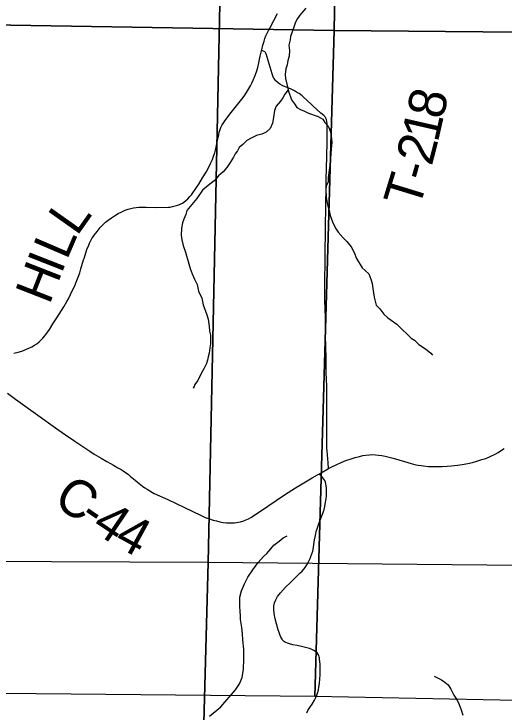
# Model space of a CAD drawing. Extents: x -19.9 to 41.9, y 0 to 32.3.
# Drawn here: x 5.525 to 6.268, y 14.677 to 15.736 of the extents above; entities that cross this region are included whole.
import ezdxf

# ---------------------------------------------------------------- set-up
doc = ezdxf.new("R2010")
doc.units = 0
for name, color, linetype in [('GM_X_Corporation', 7, 'Continuous'), ('GM_X_County_Road', 7, 'Continuous'), ('GM_X_County_Road_Text', 7, 'Continuous'), ('GM_X_Minor_River', 7, 'Continuous'), ('GM_X_Section', 7, 'Continuous'), ('GM_X_Township_Road', 7, 'Continuous'), ('GM_X_Township_Road_Text', 7, 'Continuous')]:
    doc.layers.add(name, color=color, linetype=linetype)

msp = doc.modelspace()

# ---------------------------------------------------------------- linework, layer by layer
at = {"layer": 'GM_X_Corporation'}
for points in [[(5.8404, 15.9209), (5.8188, 14.9036), (4.9872, 14.9075), (5.0009, 15.8404), (5.0026, 15.928)], [(6.8522, 15.9041), (6.8226, 14.894), (5.8188, 14.9036), (5.8404, 15.9209)], [(4.9783, 14.1), (5.7974, 14.1), (5.8188, 14.9036), (4.9872, 14.9075), (4.9863, 14.8396)], [(5.7974, 14.1), (6.8053, 14.1), (6.8226, 14.894), (5.8188, 14.9036)]]:
    msp.add_lwpolyline(points, close=True, dxfattribs=at)
at = {"layer": 'GM_X_County_Road'}
msp.add_line((5.9877, 15.0383), (6.0017, 15.0465), dxfattribs=at)
for points in [[(5.5146, 15.1607), (5.5269, 15.1516), (5.5605, 15.1273), (5.5873, 15.1082), (5.6025, 15.0977), (5.6169, 15.088), (5.6396, 15.0726), (5.6463, 15.0683), (5.657, 15.062), (5.6654, 15.0572), (5.6708, 15.0541), (5.6753, 15.0515), (5.682, 15.0476), (5.687, 15.0447), (5.6902, 15.0427), (5.6981, 15.0371), (5.7007, 15.035), (5.7083, 15.0289), (5.7145, 15.0238), (5.7193, 15.0198), (5.7229, 15.0172), (5.7266, 15.0148), (5.7346, 15.01), (5.7372, 15.0087), (5.7577, 14.9992), (5.7832, 14.9872), (5.8073, 14.9756), (5.8146, 14.9723), (5.8197, 14.9704), (5.8264, 14.9682), (5.8316, 14.9668), (5.8367, 14.9656), (5.842, 14.9646), (5.8468, 14.9641), (5.8511, 14.9639), (5.8589, 14.9641), (5.8651, 14.965), (5.8682, 14.9657), (5.873, 14.9671), (5.8753, 14.9679), (5.88, 14.97), (5.8838, 14.972), (5.8863, 14.9735), (5.9095, 14.9892), (5.9349, 15.0065), (5.9515, 15.0173), (5.9666, 15.0264), (5.9768, 15.0324), (5.9848, 15.0367), (5.9877, 15.0383)], [(6.0017, 15.0465), (6.0068, 15.049), (6.0142, 15.0527), (6.0208, 15.0556), (6.028, 15.0584), (6.0359, 15.0611), (6.0419, 15.063), (6.0484, 15.0648), (6.0537, 15.066), (6.0581, 15.0667), (6.0636, 15.0673), (6.0674, 15.0675), (6.0726, 15.0673), (6.0775, 15.0668), (6.0825, 15.0661), (6.0876, 15.0651), (6.0916, 15.0641), (6.0998, 15.0619), (6.1165, 15.0568), (6.127, 15.0538), (6.1302, 15.053), (6.1339, 15.0522), (6.1375, 15.0513), (6.142, 15.0507), (6.1458, 15.0502), (6.1531, 15.0495), (6.1586, 15.0494), (6.1673, 15.0493), (6.1737, 15.0494), (6.1815, 15.0498), (6.1882, 15.0503), (6.1971, 15.0514), (6.2043, 15.0525), (6.213, 15.0541), (6.2199, 15.0557), (6.2265, 15.0575), (6.234, 15.0598), (6.2401, 15.0618), (6.2454, 15.0639), (6.2479, 15.065), (6.2542, 15.0683), (6.259, 15.0709), (6.2625, 15.0731), (6.2678, 15.0766)]]:
    msp.add_lwpolyline(points, dxfattribs=at)
at = {"layer": 'GM_X_Minor_River'}
for points in [[(5.9671, 15.7447), (5.9582, 15.7343), (5.9534, 15.7274), (5.9508, 15.722), (5.9483, 15.7143), (5.9439, 15.7017), (5.9432, 15.6964), (5.9414, 15.6884), (5.9423, 15.6807), (5.9417, 15.672), (5.9399, 15.6651), (5.9388, 15.6586), (5.937, 15.6529), (5.936, 15.6441), (5.9361, 15.638), (5.9389, 15.6274), (5.9406, 15.6187), (5.9453, 15.6054), (5.9499, 15.5998), (5.9534, 15.5941), (5.9588, 15.5908), (5.9652, 15.5882), (5.971, 15.5852), (5.9858, 15.5805), (5.9927, 15.5764), (5.9958, 15.5715), (6.0008, 15.5659), (6.0031, 15.561), (6.0051, 15.5549), (6.0064, 15.5412), (6.0054, 15.5306), (6.0045, 15.5172), (6.0046, 15.5119), (6.0028, 15.5027), (6.0011, 15.4879), (6.0009, 15.4814), (5.9979, 15.4749), (5.9976, 15.4699), (5.9978, 15.4577), (6.0002, 15.4467), (6.0023, 15.4376), (6.0039, 15.4301), (6.0074, 15.4206), (6.0121, 15.4108), (6.0164, 15.4051), (6.0237, 15.3965), (6.0294, 15.3908), (6.036, 15.3826), (6.0403, 15.3739), (6.0442, 15.3652), (6.0524, 15.3508), (6.0573, 15.3467), (6.0627, 15.3415), (6.0655, 15.3335), (6.0678, 15.3271), (6.0687, 15.3195), (6.0696, 15.313), (6.0708, 15.3062), (6.0736, 15.2941), (6.0794, 15.2884), (6.0852, 15.2805), (6.0913, 15.2749), (6.0963, 15.2712), (6.1051, 15.2652), (6.1132, 15.2573), (6.1208, 15.2502), (6.1266, 15.2442), (6.1319, 15.2409), (6.1385, 15.2345), (6.1488, 15.2278), (6.1565, 15.2214), (6.1591, 15.2183)], [(5.9402, 15.6207), (5.9353, 15.614), (5.932, 15.6087), (5.9287, 15.6037), (5.9223, 15.5959), (5.9194, 15.5894), (5.9187, 15.5826), (5.9177, 15.5757), (5.9167, 15.57), (5.913, 15.5619), (5.907, 15.5565), (5.9006, 15.5538), (5.8923, 15.5513), (5.8844, 15.5474), (5.8777, 15.5439), (5.8717, 15.5377), (5.8661, 15.5334), (5.8635, 15.5285), (5.8602, 15.5235), (5.8572, 15.5185), (5.8524, 15.5108), (5.8472, 15.5031), (5.8416, 15.4965), (5.8349, 15.4904), (5.8282, 15.4826), (5.8192, 15.4757), (5.8106, 15.4687), (5.8017, 15.456), (5.7917, 15.444), (5.7868, 15.4379), (5.785, 15.4318), (5.7821, 15.4245), (5.7803, 15.4191), (5.7785, 15.4111), (5.7779, 15.4004), (5.7792, 15.3932), (5.7812, 15.3845), (5.7847, 15.3747), (5.7863, 15.369), (5.7875, 15.364), (5.7895, 15.3568), (5.7915, 15.35), (5.7947, 15.3417), (5.7982, 15.3337), (5.8021, 15.3254), (5.8045, 15.3152), (5.8092, 15.3046), (5.8116, 15.2947), (5.8172, 15.2796), (5.8191, 15.2728), (5.8204, 15.2621), (5.8213, 15.2549), (5.8225, 15.2488), (5.8227, 15.2355), (5.8217, 15.2294), (5.8206, 15.2214), (5.8192, 15.2157), (5.8182, 15.2107), (5.8163, 15.2057), (5.8123, 15.1977), (5.8086, 15.1904), (5.806, 15.185), (5.8027, 15.1793), (5.799, 15.1739), (5.7968, 15.1685), (5.7971, 15.1704)], [(5.873, 14.7723), (5.8717, 14.7867), (5.8712, 14.7955), (5.8699, 14.8053), (5.8682, 14.8171), (5.8681, 14.8224), (5.8676, 14.8301), (5.8671, 14.8373), (5.867, 14.8441), (5.8673, 14.8514), (5.8698, 14.8609), (5.8742, 14.8713), (5.8794, 14.8816), (5.8868, 14.8928), (5.8949, 14.9039), (5.9031, 14.9128), (5.908, 14.9174), (5.9139, 14.9244), (5.9188, 14.9302), (5.9266, 14.9364), (5.933, 14.9414), (5.9386, 14.9441)], [(5.8211, 14.6706), (5.8323, 14.6796), (5.8383, 14.685), (5.8472, 14.6954), (5.8543, 14.7035), (5.8606, 14.7108), (5.8666, 14.72), (5.8706, 14.7292), (5.8727, 14.7422), (5.8732, 14.7574), (5.873, 14.7723)], [(6.1617, 14.7316), (6.1728, 14.7257), (6.1781, 14.7224), (6.1831, 14.7183), (6.187, 14.7119), (6.1917, 14.7028), (6.1967, 14.6949), (6.1994, 14.6884), (6.2026, 14.6805), (6.2054, 14.6722)]]:
    msp.add_lwpolyline(points, dxfattribs=at)
at = {"layer": 'GM_X_Section'}
for points in [[(5.0099, 16.7619), (6.0276, 16.7357), (6.0103, 15.7106), (4.9984, 15.7274)], [(6.0276, 16.7357), (7.0463, 16.7153), (7.0239, 15.7019), (6.0103, 15.7106)], [(6.0103, 15.7106), (5.9806, 14.7005), (4.9768, 14.7102), (4.9984, 15.7274)], [(7.0239, 15.7019), (7.0016, 14.6805), (5.9806, 14.7005), (6.0103, 15.7106)]]:
    msp.add_lwpolyline(points, close=True, dxfattribs=at)
at = {"layer": 'GM_X_Township_Road'}
msp.add_line((5.9877, 15.0383), (6.0017, 15.0465), dxfattribs=at)
for points in [[(5.5242, 15.2212), (5.5307, 15.2228), (5.5363, 15.2244), (5.5401, 15.2257), (5.5472, 15.2287), (5.5515, 15.2308), (5.5559, 15.2333), (5.5593, 15.2357), (5.563, 15.2387), (5.5653, 15.2409), (5.5684, 15.2441), (5.5712, 15.2475), (5.5742, 15.2515), (5.5783, 15.2573), (5.5837, 15.2658), (5.5894, 15.2748), (5.6002, 15.2917), (5.6049, 15.2995), (5.6074, 15.304), (5.6105, 15.3103), (5.6173, 15.3248), (5.6191, 15.3292), (5.6219, 15.3365), (5.6242, 15.3432), (5.6261, 15.3495), (5.6302, 15.3627), (5.6309, 15.365), (5.6336, 15.3736), (5.6358, 15.3799), (5.6374, 15.3838), (5.6391, 15.3881), (5.6401, 15.3901), (5.6428, 15.3951), (5.644, 15.3971), (5.6463, 15.4005), (5.6486, 15.4036), (5.6506, 15.4061), (5.6554, 15.4118), (5.6579, 15.4146), (5.6604, 15.4171), (5.6636, 15.42), (5.6674, 15.4231), (5.6725, 15.4268), (5.6772, 15.4299), (5.6828, 15.4332), (5.6881, 15.4359), (5.6932, 15.4381), (5.6978, 15.4397), (5.7017, 15.4408), (5.7058, 15.4417), (5.7098, 15.4423), (5.7139, 15.4427), (5.7177, 15.4429), (5.725, 15.4427), (5.7404, 15.4422), (5.7588, 15.4427), (5.7616, 15.443), (5.7647, 15.4436), (5.7688, 15.4446), (5.7732, 15.446), (5.7765, 15.4472), (5.7799, 15.449), (5.7823, 15.4505), (5.7852, 15.4529), (5.788, 15.4555), (5.7914, 15.4592), (5.7936, 15.4617), (5.8013, 15.4724), (5.8049, 15.4779), (5.8106, 15.4874), (5.8158, 15.4961), (5.8204, 15.5045), (5.8226, 15.5089), (5.8254, 15.515), (5.8273, 15.52), (5.829, 15.525), (5.8302, 15.5294), (5.8312, 15.5338), (5.8327, 15.5417), (5.8351, 15.5526), (5.8359, 15.5566), (5.8371, 15.5605), (5.8383, 15.5638), (5.8403, 15.5678), (5.8427, 15.5715), (5.8445, 15.574), (5.8541, 15.5866), (5.8701, 15.6066), (5.8735, 15.6114), (5.8771, 15.6168), (5.8801, 15.6218), (5.883, 15.6267), (5.8853, 15.631), (5.8875, 15.6356), (5.8898, 15.6416), (5.8921, 15.6483), (5.8941, 15.6548), (5.8959, 15.6618), (5.8981, 15.6719), (5.8999, 15.6802), (5.9002, 15.6816), (5.902, 15.6886), (5.9038, 15.6945), (5.9052, 15.6987), (5.9067, 15.7026), (5.9105, 15.7107), (5.9128, 15.7153), (5.9241, 15.7364)], [(6.0017, 15.0465), (6.0009, 15.0549), (5.9993, 15.0731), (5.9991, 15.0766), (5.999, 15.0815), (5.9988, 15.1708), (5.9984, 15.1821), (5.9981, 15.1916), (5.998, 15.2022), (5.9978, 15.2204), (5.9977, 15.2239), (5.9976, 15.2291), (5.9975, 15.2324), (5.9973, 15.237), (5.9972, 15.2417), (5.997, 15.248), (5.9968, 15.2565), (5.9968, 15.2672), (5.9967, 15.2753), (5.9961, 15.3011), (5.9958, 15.3219), (5.996, 15.341), (5.9962, 15.3504), (5.9964, 15.3599), (5.9965, 15.3649), (5.9966, 15.373), (5.997, 15.4069), (5.9971, 15.4151), (5.9976, 15.4415), (5.9977, 15.4508), (5.998, 15.4683), (5.9982, 15.4843), (5.999, 15.5198), (5.9997, 15.5425), (5.9995, 15.5683), (5.9994, 15.5695), (5.9984, 15.5758), (5.9981, 15.5769), (5.9972, 15.5787), (5.9965, 15.5798), (5.9944, 15.5818), (5.9901, 15.5856), (5.9778, 15.5964), (5.9751, 15.599), (5.9629, 15.6103), (5.9614, 15.6117), (5.9568, 15.6152), (5.9546, 15.6165), (5.9501, 15.6191), (5.9451, 15.6216), (5.9389, 15.6242), (5.9333, 15.6265), (5.931, 15.6275), (5.9275, 15.6295), (5.9251, 15.6313), (5.9223, 15.6337), (5.9209, 15.6351), (5.9189, 15.6378), (5.9183, 15.639), (5.9163, 15.6453), (5.907, 15.6754), (5.9065, 15.6766), (5.9058, 15.6776), (5.9052, 15.6782), (5.9041, 15.6787), (5.9012, 15.6798), (5.8999, 15.6802)], [(5.9687, 14.6758), (5.9704, 14.6793), (5.9731, 14.6837), (5.9767, 14.689), (5.9802, 14.6952), (5.9821, 14.6989), (5.9837, 14.7024), (5.9848, 14.7056), (5.9861, 14.7104), (5.9869, 14.7148), (5.9879, 14.7205), (5.9886, 14.7271), (5.9889, 14.7335), (5.989, 14.7445), (5.9889, 14.7493), (5.9886, 14.7535), (5.9881, 14.7573), (5.9878, 14.7593), (5.9875, 14.7609), (5.9869, 14.7625), (5.9861, 14.7639), (5.9852, 14.7655), (5.9841, 14.7669), (5.9818, 14.7689), (5.9792, 14.7705), (5.9764, 14.772), (5.9726, 14.7733), (5.9668, 14.775), (5.9605, 14.7763), (5.9538, 14.7777), (5.9476, 14.7791), (5.9422, 14.7805), (5.9395, 14.7812), (5.9369, 14.7822), (5.9349, 14.7833), (5.9335, 14.7846), (5.9322, 14.7857), (5.931, 14.7874), (5.93, 14.7888), (5.9291, 14.7907), (5.9283, 14.7931), (5.9267, 14.7974), (5.9254, 14.8017), (5.9227, 14.8106), (5.9207, 14.8182), (5.9191, 14.8265), (5.9185, 14.8328), (5.9187, 14.8382), (5.9196, 14.8425), (5.9214, 14.8472), (5.9244, 14.8522), (5.9285, 14.8579), (5.9362, 14.8663), (5.9437, 14.8733), (5.9582, 14.8874), (5.9614, 14.8909), (5.9659, 14.8964), (5.9684, 14.9003), (5.9711, 14.905), (5.9736, 14.91), (5.9749, 14.9128), (5.9764, 14.917), (5.9776, 14.9211), (5.9786, 14.9264), (5.9792, 14.931), (5.9802, 14.9383), (5.9816, 14.9449), (5.983, 14.9508), (5.9842, 14.955), (5.9857, 14.9594), (5.9875, 14.964), (5.9915, 14.9744), (5.9932, 14.9794), (5.9947, 14.984), (5.996, 14.9889), (5.9972, 14.9951), (5.9979, 15.0005), (5.9984, 15.0052), (5.9987, 15.0097), (5.9986, 15.0166), (5.9982, 15.02), (5.9976, 15.023), (5.9968, 15.0256), (5.9957, 15.028), (5.9943, 15.0303), (5.9908, 15.0347), (5.9889, 15.0369), (5.9877, 15.0383)]]:
    msp.add_lwpolyline(points, dxfattribs=at)

# ---------------------------------------------------------------- texts
at = {"layer": 'GM_X_County_Road_Text'}
for s, rotation, p in [('C', 325.8163, (5.582, 14.9932)), ('-', 325.8702, (5.6207, 14.967)), ('4', 326.0756, (5.6402, 14.9538)), ('4', 331.4263, (5.6742, 14.9312))]:
    msp.add_text(s, height=0.0568, rotation=rotation, dxfattribs=at).set_placement(p)
at = {"layer": 'GM_X_Township_Road_Text'}
for s, rotation, p in [('8', 77.7505, (6.175, 15.5744)), ('1', 77.1601, (6.1671, 15.5396)), ('2', 75.6437, (6.158, 15.5041)), ('-', 74.1568, (6.1512, 15.4801)), ('T', 72.9366, (6.1384, 15.4382)), ('L', 54.7134, (5.6199, 15.3977)), ('L', 66.766, (5.6047, 15.3614)), ('I', 68.5421, (5.5964, 15.3402)), ('H', 68.6471, (5.5782, 15.2936))]:
    msp.add_text(s, height=0.0568, rotation=rotation, dxfattribs=at).set_placement(p)

doc.saveas('drawing.dxf')
